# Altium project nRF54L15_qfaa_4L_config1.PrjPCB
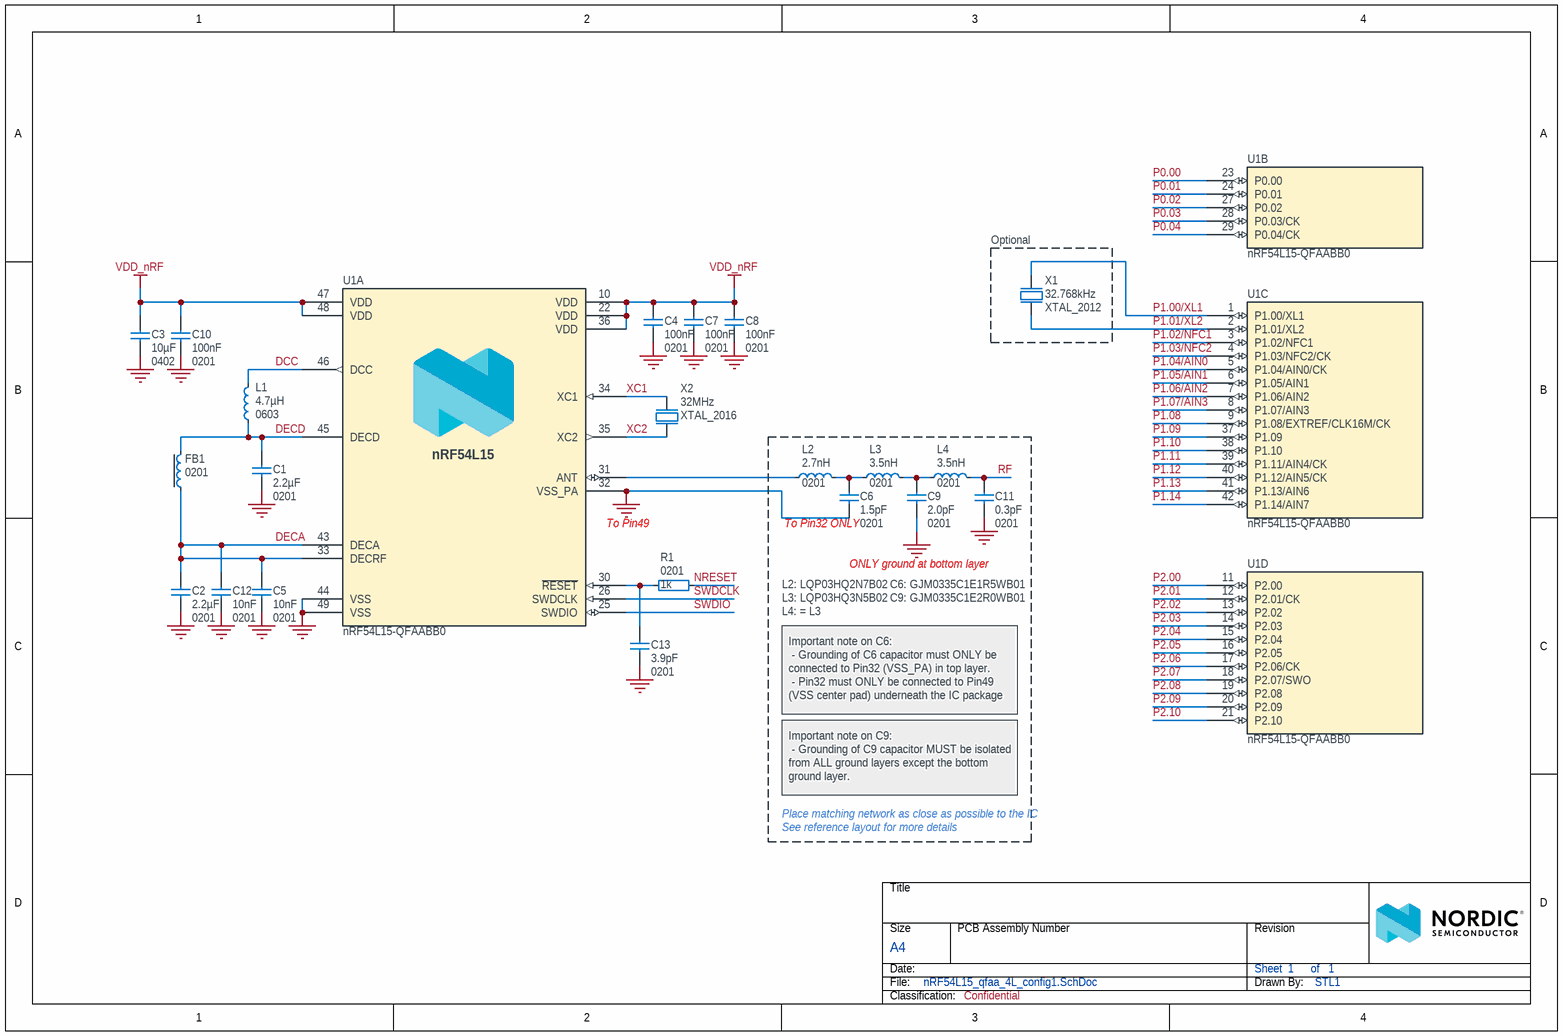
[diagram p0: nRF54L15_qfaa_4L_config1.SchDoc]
Classification: Confidential; DrawnBy: STL1; PCARevision: =Revision; Revision: =Revision
1 sheet, 22 parts. Net scope: global (net labels, ports and power ports of the same name join across sheets).
Board file: nRF54L15_qfaa_4L_config1.PcbDoc

## Sheet nRF54L15_qfaa_4L_config1.SchDoc: =BoardTitle
size A4; Device: nRF54L15-QFAA; RefLayoutTitle: Reference Layout; Organization: Nordic Semiconductor; DocumentNumber: 1; SheetNumber: 1; SheetTotal: 1; CompanyName: Nordic Semiconductor; DocumentSize: A4

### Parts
C1  2.2µF  Footprint Doc: 0201  [CAPC0603X03L_C]
C2  2.2µF  Footprint Doc: 0201  [CAPC0603X03L_C]
C3  10µF  Footprint Doc: 0402  [CAPC1005X04L]
C4  100nF  Footprint Doc: 0201  [CAPC0603X03L_C]
C5  10nF  Footprint Doc: 0201  [CAPC0603X03L_C]
C6  1.5pF  Footprint Doc: 0201  [CAPC0603X03L_C]
C7  100nF  Footprint Doc: 0201  [CAPC0603X03L_C]
C8  100nF  Footprint Doc: 0201  [CAPC0603X03L_C]
C9  2.0pF  Footprint Doc: 0201  [CAPC0603X03L_C]
C10  100nF  Footprint Doc: 0201  [CAPC0603X03L_C]
C11  0.3pF  Footprint Doc: 0201  [CAPC0603X03L_C]
C12  10nF  Footprint Doc: 0201  [CAPC0603X03L_C]
C13  3.9pF  Footprint Doc: 0201  [CAPC0603X03L_C]
FB1  Footprint Doc: 0201  [INDC0603X03L_C]  (hidden comment: 120R/0.2A)
L1  4.7µH  Footprint Doc: 0603  [INDC1608X06L]
L2  2.7nH  Footprint Doc: 0201  [INDC0603X03L_C]
L3  3.5nH  Footprint Doc: 0201  [INDC0603X03L_C]
L4  3.5nH  Footprint Doc: 0201  [INDC0603X03L_C]
R1  1k  Footprint Doc: 0201  [RESC0603X03L_C]
U1  nRF54L15-QFAABB0  [QFN40P600X600X90-48N]  (parts A,B,C,D of 4)
X1  32.768kHz  [XTAL_2012]
X2  32MHz  Footprint Doc: XTAL_2016  [BT-XTAL_2016]

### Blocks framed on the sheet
Optional: X1

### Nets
GND: C1.1 C2.1 C3.1 C4.2 C5.1 C6.1 C7.2 C8.2 C9.1 C10.2 C11.1 C12.1 C13.1 U1.32(VSS_PA) U1.44(VSS) U1.49(VSS) X2.2(GND) X2.4(GND)
VDD_nRF: C3.2 C4.1 C7.1 C8.1 C10.1 U1.10(VDD) U1.22(VDD) U1.36(VDD) U1.47(VDD) U1.48(VDD)
DCC: L1.1 U1.46(DCC)
DECA: C2.2 C5.2 C12.2 FB1.2 U1.33(DECRF) U1.43(DECA)
DECD: C1.2 FB1.1 L1.2 U1.45(DECD)
NRESET: R1.2
P0.00: U1.23(P0.00)
P0.01: U1.24(P0.01)
P0.02: U1.27(P0.02)
P0.03: U1.28(P0.03/CK)
P0.04: U1.29(P0.04/CK)
P1.00/XL1: U1.1(P1.00/XL1) X1.2(out)
P1.01/XL2: U1.2(P1.01/XL2) X1.1(inp)
P1.02/NFC1: U1.3(P1.02/NFC1)
P1.03/NFC2: U1.4(P1.03/NFC2/CK)
P1.04/AIN0: U1.5(P1.04/AIN0/CK)
P1.05/AIN1: U1.6(P1.05/AIN1)
P1.06/AIN2: U1.7(P1.06/AIN2)
P1.07/AIN3: U1.8(P1.07/AIN3)
P1.08: U1.9(P1.08/EXTREF/CLK16M/CK)
P1.09: U1.37(P1.09)
P1.10: U1.38(P1.10)
P1.11: U1.39(P1.11/AIN4/CK)
P1.12: U1.40(P1.12/AIN5/CK)
P1.13: U1.41(P1.13/AIN6)
P1.14: U1.42(P1.14/AIN7)
P2.00: U1.11(P2.00)
P2.01: U1.12(P2.01/CK)
P2.02: U1.13(P2.02)
P2.03: U1.14(P2.03)
P2.04: U1.15(P2.04)
P2.05: U1.16(P2.05)
P2.06: U1.17(P2.06/CK)
P2.07: U1.18(P2.07/SWO)
P2.08: U1.19(P2.08)
P2.09: U1.20(P2.09)
P2.10: U1.21(P2.10)
RF: C11.2 L4.2
SWDCLK: U1.26(SWDCLK)
SWDIO: U1.25(SWDIO)
XC1: U1.34(XC1) X2.1(inp)
XC2: U1.35(XC2) X2.3(out)
NetC6_2: C6.2 L2.2 L3.1
NetC9_2: C9.2 L3.2 L4.1
NetC13_2: C13.2 R1.1 U1.30(~{RESET})
NetL2_1: L2.1 U1.31(ANT)

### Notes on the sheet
- (near U1) To Pin49
- (near C6) To Pin32 ONLY
- ONLY ground at bottom layer
- L2: LQP03HQ2N7B02
- L3: LQP03HQ3N5B02
- L4: = L3
- C6: GJM0335C1E1R5WB01
- C9: GJM0335C1E2R0WB01
- Important note on C6:
  - Grounding of C6 capacitor must ONLY be connected to Pin32 (VSS_PA) in top layer.
  - Pin32 must ONLY be connected to Pin49 (VSS center pad) underneath the IC package
- Important note on C9:
  - Grounding of C9 capacitor MUST be isolated from ALL ground layers except the bottom ground layer.
- See reference layout for more details
- Place matching network as close as possible to the IC

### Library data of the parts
C1 C2 = C0201-2µ2-2.5V-X6T-GRM033D80E225ME47D: Capacitor, Ceramic, 2.2µF 2.5V X6T 0201,±20%; Manufacturer: Murata; Manufacturer Part Number: GRM033R61A225KE47; Part number NEMS: 100200527; Component Status: Active; Pad Count: 2; Note: 2.5V, 20%, X6T; Artikkelnr Noca: N.A.
C3 = C0402-10µF-6.3V-X6S: Capacitor, X6S, ±20%, 6.3V; Manufacturer: N.A.; Part number NEMS: 100200478; Component Status: Active; Pad Count: 2
C4 C7 C8 C10 = C0201-100n-10V-X7R: Capacitor, X7R, ±10%; Manufacturer: N.A.; Part number NEMS: 100200469; Note: 10V; Pad Count: 2; Component Status: Active
C5 C12 = C0201-10n-6.3V-X7R: Capacitor, X7R, 6.3V; Manufacturer: Murata; Manufacturer Part Number: GRM033R70J103KA01D; Part number NEMS: 100200407; Component Status: Active; Pad Count: 2; Artikkelnr Noca: N.A.
C6 = C0201-1.5p-25V-NP0-GJM0335C1E1R5WB01: Capacitor, NP0, ±0.05pF, 25V, High Q; Manufacturer: Murata; Part number NEMS: 100200477; Component Status: Active; Pad Count: 2; Artikkelnr Noca: N.A.
C9 = C0201-2.0p-HQ-Murata: Capacitor, NP0, ±0.05pF, 25V; Manufacturer: Murata; Manufacturer Part Number: GJM0335C1E2R0WB01; Part number IPS: 00000001775; Part number NEMS: 100200419; Component Status: Active; Pad Count: 2; Artikkelnr Noca: N.A.
C11 = C0201-0.3p-50V-GRM0335C1HR30BA01: Capacitor, C0G, ±0.1pF, 50V; Manufacturer: Murata; Part number NEMS: 100200650; Component Status: Active; Pad Count: 2; Artikkelnr Noca: N.A.
C13 = C0201-3.9p: Chip Cap 0201; Manufacturer: N.A.; Part number NEMS: 100200024; Component Status: Active; Pad Count: 2; Note: Chip Cap 1%
FB1 = FB0201-120R@100M-200mA-BLM03AG121SN1D: Ferrite Bead, 120 Ohm @ 100MHz, 200mA, 500 mOhm Max; Manufacturer: Murata; Part number NEMS: 100300419; Component Status: Active; Pad Count: 2; Artikkelnr Noca: N.A.
L1 = L0603-4µ7-MLZ1608M4R7WT000: Inductor, 120mA, ±20%, 0.65R; Manufacturer: TDK Corporation; Part number NEMS: 100300440; Component Status: Active; Pad Count: 2; Note: Power Inductor ±20%; Artikkelnr Noca: N.A.
L2 = L0201-2n7-HQ-Murata: Inductor, 600mA, ±0.1ｎH, 120mOhm; Manufacturer: Murata; Manufacturer Part Number: LQP03HQ2N7B02; Part number IPS: 00000001753; Part number NEMS: 100300214; Component Status: Active; Pad Count: 2; Note: -55°C ~ 125°C; Artikkelnr Noca: N.A.
L3 L4 = L0201-3n5-HQ-Murata: Inductor, 500mA, ±0.1ｎH, 170mOhm; Manufacturer: Murata; Manufacturer Part Number: LQP03HQ3N5B02; Part number NEMS: 100300222; Component Status: Active; Pad Count: 2; Note: -55°C ~ 125°C; Artikkelnr Noca: N.A.
R1 = R0201-1k0: Resistor, ±1%, 0.05W; Manufacturer: N.A.; Part number IPS: 00000005786; Part number NEMS: 100100043; Component Status: Active; Pad Count: 2; Note: Chip Res 1%
U1 = nRF54L15-QFAABB0: Multi-protocol Bluetooth Low Energy, IEEE 802.15.4, ANT and 2.4GHz proprietary system-on-chip; Manufacturer: Nordic Semiconductor; Part number NEMS: 102000348; Component Status: Active; Pad Count: 49; Note: N.A.
X1 = XTAL_SMD2012_32.768kHz_9pF_TXC: XTAL SMD 2012, 32.768kHz, 9pF, ±20ppm; Manufacturer: TXC Corporation; Manufacturer Part Number: 9HT11-32.768KDZC-T; Part number NEMS: 101600107; Component Status: Active; Pad Count: 2; Note: XTAL SMD 32.768kHz; Artikkelnr Noca: N.A.
X2 = XTAL_SMD2016_32MHz_8pF_Kyocera: XTAL SMD 2016, 32MHz, Cl=8pF, Tot: ±40ppm; Manufacturer Part Number: CX2016DB32000D0WZRC1; Part number IPS: 00000007827; Part number Norautron: 26511136; Part number NEMS: 101600039; Component Status: Active; Pad Count: 4; Note: XTAL SMD 32.000MHz; Artikkelnr Noca: 22010022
